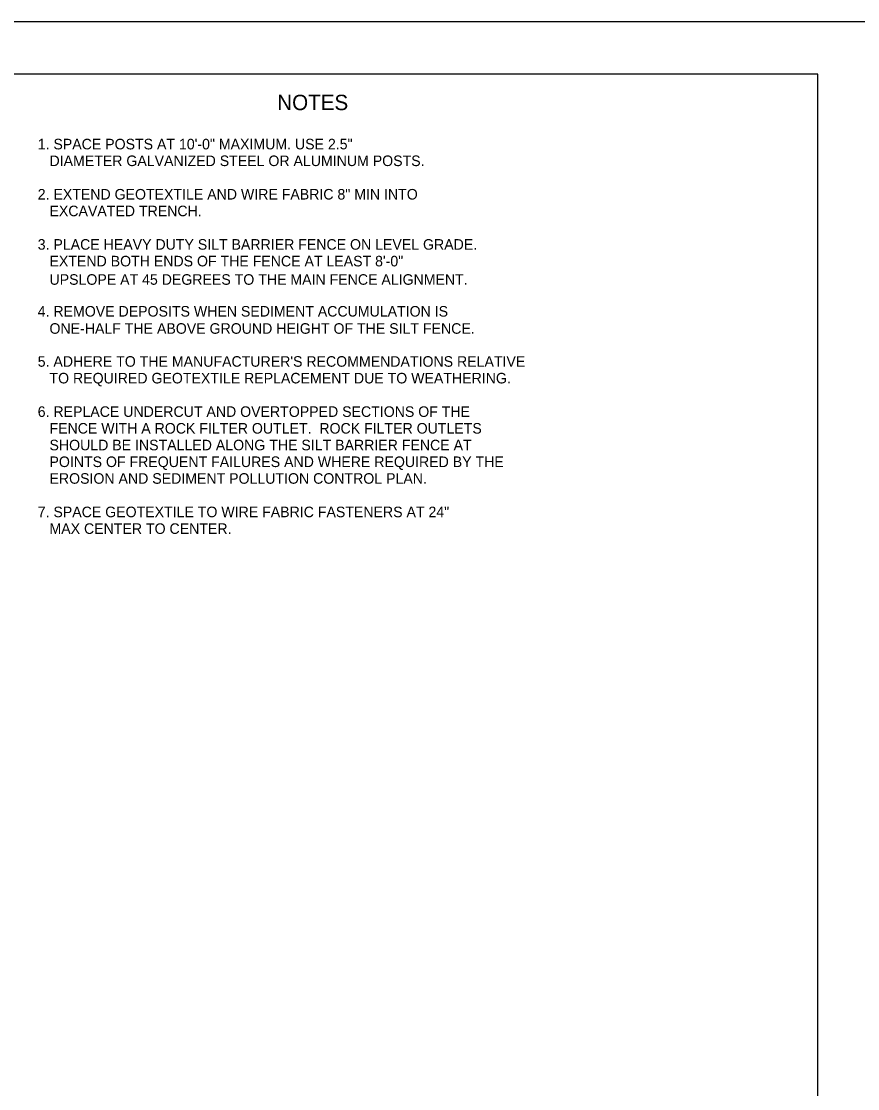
# Model space of a CAD drawing. Extents: x 636462 to 639049, y 299944 to 300538.
# Drawn here: x 637902.8 to 638140.2, y 300235.4 to 300538.4 of the extents above; entities that cross this region are included whole.
import ezdxf

# ---------------------------------------------------------------- set-up
doc = ezdxf.new("R2010")
doc.units = 0
for name, color, linetype in [('1', 7, 'Continuous'), ('Default', 7, 'Continuous'), ('PLT-BNDY', 7, 'Continuous')]:
    doc.layers.add(name, color=color, linetype=linetype)

msp = doc.modelspace()

# ---------------------------------------------------------------- linework, layer by layer
at = {"layer": '1'}
msp.add_lwpolyline([(638128.91, 299959.45), (638128.91, 300523.45), (637342.91, 300523.45), (637342.91, 299959.45), (638128.91, 299959.45), (638128.91, 299985.81), (637928.91, 299985.81), (637928.91, 300050.49), (638128.91, 300050.49), (638128.91, 300079.45), (637928.91, 300079.45), (637928.91, 299959.45), (638007.72, 299959.45), (638007.72, 299985.81), (638007.72, 299959.45), (638084.72, 299959.45), (638084.72, 299985.81), (638084.72, 299973.49), (638128.91, 299973.49)], dxfattribs=at)
at = {"layer": 'PLT-BNDY'}
msp.add_lwpolyline([(637302.91, 300538.45), (638143.91, 300538.45), (638143.91, 299944.45), (637302.91, 299944.45)], close=True, dxfattribs=at)

# ---------------------------------------------------------------- texts
at = {"layer": 'Default'}
for s, height, p in [('NOTES', 4.372, (637975.41, 300513.24)), ('1. SPACE POSTS AT 10\'-0" MAXIMUM. USE 2.5"', 2.998, (637907.4, 300502.1)), ('2. EXTEND GEOTEXTILE AND WIRE FABRIC 8" MIN INTO', 2.998, (637907.4, 300487.86)), ('   EXTEND BOTH ENDS OF THE FENCE AT LEAST 8\'-0"', 2.998, (637907.4, 300468.88)), ('   UPSLOPE AT 45 DEGREES TO THE MAIN FENCE ALIGNMENT.', 2.998, (637907.4, 300463.66)), ('7. SPACE GEOTEXTILE TO WIRE FABRIC FASTENERS AT 24"', 2.998, (637907.4, 300397.67))]:
    msp.add_text(s, height=height, dxfattribs=at).set_placement(p)
for s, p in [('   DIAMETER GALVANIZED STEEL OR ALUMINUM POSTS.', (637907.4, 300497.36)), ('   EXCAVATED TRENCH.', (637907.4, 300483.12)), ('3. PLACE HEAVY DUTY SILT BARRIER FENCE ON LEVEL GRADE. ', (637907.4, 300473.62)), ('4. REMOVE DEPOSITS WHEN SEDIMENT ACCUMULATION IS ', (637907.4, 300454.63)), ('   ONE-HALF THE ABOVE GROUND HEIGHT OF THE SILT FENCE.', (637907.4, 300449.75)), ("5. ADHERE TO THE MANUFACTURER'S RECOMMENDATIONS RELATIVE", (637907.4, 300440.39)), ('   TO REQUIRED GEOTEXTILE REPLACEMENT DUE TO WEATHERING.', (637907.4, 300435.65)), ('6. REPLACE UNDERCUT AND OVERTOPPED SECTIONS OF THE  ', (637907.4, 300426.15)), ('   FENCE WITH A ROCK FILTER OUTLET.  ROCK FILTER OUTLETS', (637907.4, 300421.41)), ('   SHOULD BE INSTALLED ALONG THE SILT BARRIER FENCE AT', (637907.4, 300416.66)), ('   POINTS OF FREQUENT FAILURES AND WHERE REQUIRED BY THE', (637907.4, 300411.91)), ('   EROSION AND SEDIMENT POLLUTION CONTROL PLAN.', (637907.4, 300407.17)), ('   MAX CENTER TO CENTER.', (637907.4, 300392.93))]:
    msp.add_text(s, height=2.998, rotation=360, dxfattribs=at).set_placement(p)

doc.saveas('drawing.dxf')
